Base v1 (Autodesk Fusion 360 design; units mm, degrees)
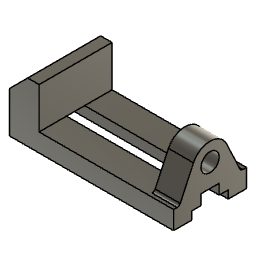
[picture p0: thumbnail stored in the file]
sketch "Sketch1" plane through (0, 0, 0) normal (0, 1, 0) x axis (1, 0, 0)
  line L1 (144, 0) -> (0, 0)
  line L2 (144, -16) -> (144, 0)
  line L3 (26, -16) -> (144, -16)
  line L4 (26, -52) -> (26, -16)
  line L5 (16, -52) -> (26, -52)
  line L6 (0, -36) -> (16, -52)
  line L7 (0, 0) -> (0, -36)
  point P1 (0, 0)
  point P2 (0, 0)
  point P9 (0, 0)
  point P3 (144, 0)
  point P6 (26, -52)
  point P7 (16, -52)
  point P8 (0, -36)
  coincident P1 P2
  horizontal L1
  perpendicular L1 L2
  perpendicular L2 L3
  perpendicular L3 L4
  perpendicular L4 L5
  coincident P1 P9
  perpendicular L1 L7
  dimension "d7" distance P2 P3 = 144
  dimension "d8" distance P6 P7 = 10
  dimension "d9" distance P7 P8 = 16
  dimension "d10" distance L1 L3 = 16
  dimension "d11" distance L3 P6 = 36
  dimension "d12" distance P7 P8 = 16
extrude "Extrude1" new body sketch "Sketch1" distance 64
sketch "Sketch2" plane through (144, 0, 0) normal (1, 0, 0) x axis (0, 1, 0)
  line L1 (32, 0) -> (-32, 0)
  line L2 (32, 16) -> (32, 0)
  line L3 (-32, 16) -> (32, 16)
  line L4 (-32, 0) -> (-32, 16)
  line L5 (-14.5009, 42.7619) -> (-26.9802, 16)
  line L6 (26.9802, 16) -> (14.5009, 42.7619)
  line L7 (-26.9802, 16) -> (26.9802, 16)
  line L8 (32, 52) -> (-32, 52)
  line L9 (0, 63.2123) -> (0, 0)
  arc A1 centre (0, 36) radius 16 clockwise from (-14.5009, 42.7619) to (14.5009, 42.7619)
  circle C1 centre (0, 36) radius 8
  point P1 (0, 0)
  point P14 (0, 0)
  point P9 (0, 36)
  point P10 (-26.9802, 16)
  point P8 (26.9802, 16)
  tangent L5 A1
  tangent A1 L6
  concentric A1 C1
  tangent A1 L8
  coincident P1 P14
  perpendicular L1 L9
  coincident P9 L9
  coincident L3 P10
  coincident L3 P8
  symmetric L5 L6 L9
  dimension "d15" radius A1 = 16
  dimension "d16" diameter C1 = 16
  dimension "d17" angle L5 L6 = 50
extrude "Extrude2" add sketch "Sketch2" profile of L3 L5 A1 L6 L7 C1 L9 against normal blind 22
sketch "Sketch3" plane through (144, 0, 0) normal (1, 0, 0) x axis (0, 1, 0)
  line L1 (32, 0) -> (-32, 0)
  line L2 (32, 16) -> (32, 0)
  line L3 (26.9802, 16) -> (32, 16)
  line L4 (14.5009, 42.7619) -> (26.9802, 16)
  line L5 (-26.9802, 16) -> (-14.5009, 42.7619)
  line L6 (-32, 16) -> (-26.9802, 16)
  line L7 (-32, 0) -> (-32, 16)
  line L8 (16, 0) -> (16, 7)
  line L9 (32, 0) -> (-32, 0)
  line L10 (-16, 7) -> (-16, 0)
  line L11 (-8, 7) -> (-16, 7)
  line L12 (-8, 16) -> (-8, 7)
  line L13 (8, 16) -> (-8, 16)
  line L14 (8, 7) -> (8, 16)
  line L15 (16, 7) -> (8, 7)
  line L16 (0, 21.8594) -> (0, 0)
  circle C1 centre (0, 36) radius 8
  arc A1 centre (0, 36) radius 16 clockwise from (-14.5009, 42.7619) to (14.5009, 42.7619)
  point P17 (-16, 0)
  point P19 (16, 0)
  point P3 (-32, 0)
  point P1 (0, 0)
  point P21 (0, 0)
  point P15 (-16, 7)
  coincident P17 L9
  perpendicular L9 L10
  perpendicular L10 L11
  perpendicular L11 L12
  perpendicular L11 L14
  perpendicular L14 L15
  coincident P19 L9
  perpendicular L8 L9
  coincident P3 L9
  equal L8 L10
  coincident P1 P21
  perpendicular L1 L16
  symmetric L8 L10 L16
  dimension "d20" distance L8 L10 = 32
  dimension "d21" distance L12 L14 = 16
  dimension "d22" distance P15 P17 = 7
  dimension "d23" distance L9 L13 = 16
extrude "Extrude3" cut sketch "Sketch3" profile of L1 L8 L9 L10 L11 L12 L13 L14 L15 L16 against normal blind 210
sketch "Sketch4" plane through (0, 0, 0) normal (0, 0, -1) x axis (1, 0, 0)
  line L1 (144, 16) -> (0, 16)
  line L2 (144, 32) -> (144, 16)
  line L3 (0, 32) -> (144, 32)
  line L4 (0, 16) -> (0, 32)
  line L5 (106, 22) -> (36, 22)
  line L6 (106, -22) -> (106, 22)
  line L7 (36, -22) -> (106, -22)
  line L8 (36, 22) -> (36, -22)
  line L9 (161, 0) -> (0, 0)
  circle C1 centre (106, 22) radius 3
  circle C2 centre (106, -22) radius 3
  circle C3 centre (36, -22) radius 3
  circle C4 centre (36, 22) radius 3
  point P1 (0, 0)
  point P10 (0, 0)
  point P7 (106, 22)
  point P12 (106, 22)
  point P8 (106, -22)
  point P13 (106, -22)
  point P9 (36, -22)
  point P14 (36, -22)
  point P6 (36, 22)
  point P15 (36, 22)
  point P3 (144, 16)
  horizontal L5
  vertical L6
  horizontal L7
  vertical L8
  coincident P1 P10
  parallel L1 L9
  symmetric L5 L7 L9
  coincident P7 P12
  coincident P8 P13
  coincident P9 P14
  coincident P6 P15
  equal C1 C4
  equal C3 C4
  equal C2 C3
  dimension "d26" distance L5 L7 = 44
  dimension "d27" distance P8 P9 = 70
  dimension "d28" distance P3 L6 = 38
  dimension "d29" diameter C1 = 6
extrude "Extrude4" cut sketch "Sketch4" profile of L5 L6 L7 L8 C1 C2 C3 C4 against normal blind 10
fillet "Fillet1" radius 3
